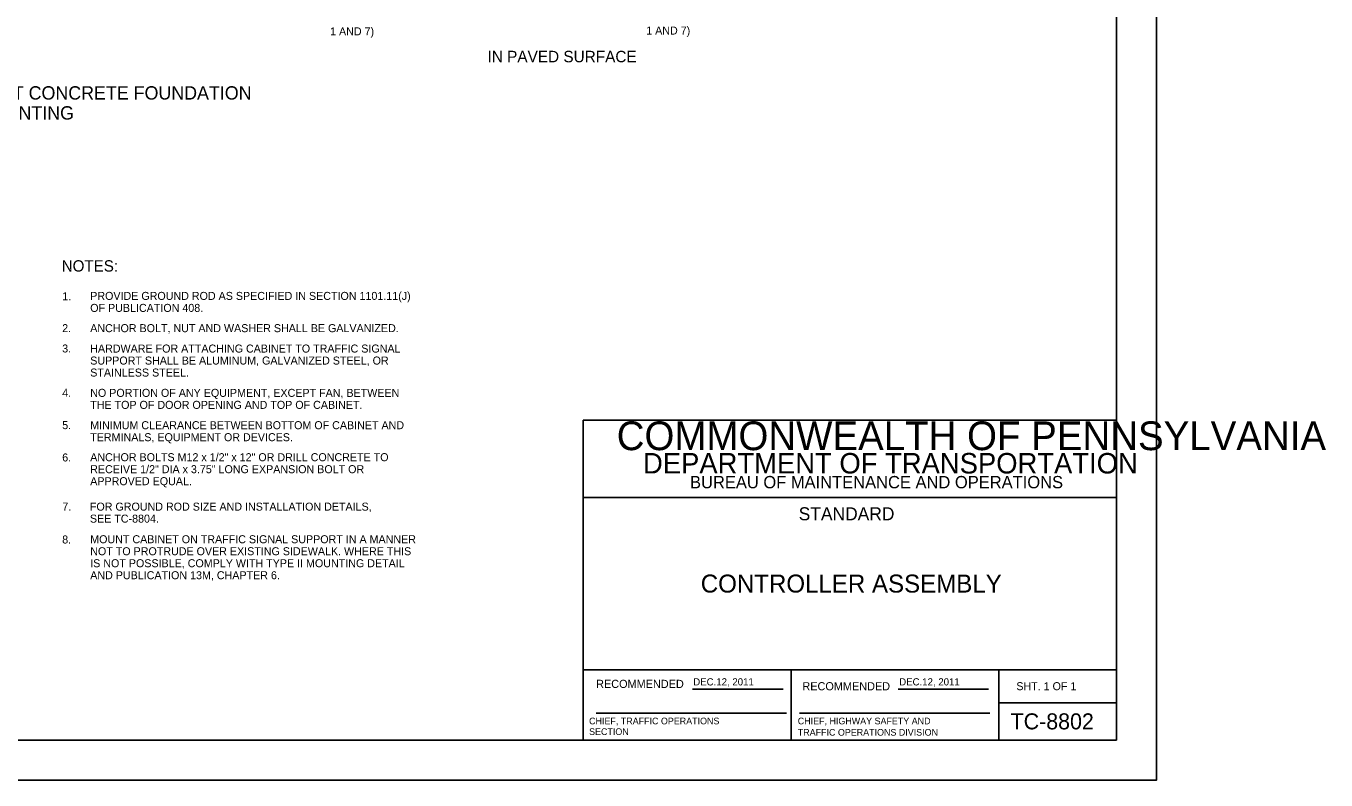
# Model space of a CAD drawing. Extents: x -855 to 49, y 616 to 1210.
# Drawn here: x -438 to 49.4, y 616.2 to 899 of the extents above; entities that cross this region are included whole.
import ezdxf

# ---------------------------------------------------------------- set-up
doc = ezdxf.new("R2010")
doc.units = 0
for name, color, linetype in [('1', 7, 'Continuous'), ('2', 7, 'Continuous'), ('4', 7, 'Continuous'), ('Default', 7, 'Continuous'), ('PLT-BNDY', 7, 'Continuous')]:
    doc.layers.add(name, color=color, linetype=linetype)

msp = doc.modelspace()

# ---------------------------------------------------------------- linework, layer by layer
at = {"layer": '1'}
for p, q in [((-29.14, 631.17), (-29.14, 1195.17)), ((-229.14, 631.17), (-229.14, 751.17)), ((-229.14, 751.17), (-29.14, 751.17)), ((-29.14, 722.17), (-229.14, 722.17)), ((-229.14, 657.55), (-29.14, 657.55)), ((-151.14, 657.55), (-151.14, 631.17)), ((-73.27, 631.17), (-73.27, 657.55)), ((-188.1, 650.2), (-154.18, 650.2)), ((-111.01, 650.2), (-77.09, 650.2)), ((-73.27, 645.17), (-29.14, 645.17)), ((-224.26, 641.21), (-152.93, 641.21)), ((-148.05, 641.21), (-76.59, 641.21)), ((-29.14, 631.17), (-815.14, 631.17)), ((-815.14, 631.17), (-229.14, 631.17))]:
    msp.add_line(p, q, dxfattribs=at)
at = {"layer": 'PLT-BNDY'}
msp.add_lwpolyline([(-855.14, 1210.17), (-14.14, 1210.17), (-14.14, 616.17), (-855.14, 616.17)], close=True, dxfattribs=at)

# ---------------------------------------------------------------- texts
at = {"layer": '1'}
for s, height, p in [('COMMONWEALTH OF PENNSYLVANIA', 10.7828, (-216.55, 739.9)), ('DEPARTMENT OF TRANSPORTATION', 7.6837, (-206.69, 731.15)), ('BUREAU OF MAINTENANCE AND OPERATIONS', 4.6253, (-189.05, 725.59)), ('CONTROLLER ASSEMBLY', 6.75, (-185.03, 686.48)), ('RECOMMENDED', 3.0516, (-224.27, 650.7)), ('RECOMMENDED', 3.0516, (-146.92, 649.82)), ('SHT. 1 OF 1', 3, (-66.71, 649.86)), ('TC-8802', 6, (-68.86, 635.17))]:
    msp.add_text(s, height=height, dxfattribs=at).set_placement(p)
at = {"layer": '2'}
for s, height, p in [('1 AND 7)', 3, (-324.01, 895.49)), ('1 AND 7)', 3, (-205.48, 895.79)), ('IN PAVED SURFACE', 4.3, (-264.98, 885.39)), ('CONTROLLER ASSEMBLY ON CEMENT CONCRETE FOUNDATION', 5, (-564.48, 871.41)), ('TYPE I MOUNTING', 5, (-479.48, 863.91)), ('NOTES:', 4.25, (-424.66, 806.89)), ('PROVIDE GROUND ROD AS SPECIFIED IN SECTION 1101.11(J) ', 3, (-413.96, 796.26)), ('1.', 3, (-424.41, 796.15)), ('OF PUBLICATION 408.', 3, (-413.96, 791.76)), ('2.', 3, (-424.46, 784.16)), ('ANCHOR BOLT, NUT AND WASHER SHALL BE GALVANIZED.', 3, (-413.96, 784.16)), ('3.', 3, (-424.46, 776.54)), ('SUPPORT SHALL BE ALUMINUM, GALVANIZED STEEL, OR', 3, (-413.96, 772.01)), ('HARDWARE FOR ATTACHING CABINET TO TRAFFIC SIGNAL', 3, (-413.96, 776.51)), ('STAINLESS STEEL.', 3, (-413.96, 767.51)), ('4.', 3, (-424.46, 759.91)), ('NO PORTION OF ANY EQUIPMENT, EXCEPT FAN, BETWEEN', 3, (-413.96, 759.89)), ('THE TOP OF DOOR OPENING AND TOP OF CABINET.', 3, (-413.96, 755.39)), ('5.', 3, (-424.46, 747.79)), ('MINIMUM CLEARANCE BETWEEN BOTTOM OF CABINET AND', 3, (-413.96, 747.76)), ('TERMINALS, EQUIPMENT OR DEVICES.', 3, (-413.96, 743.26)), ('6.', 3, (-424.46, 735.66)), ('ANCHOR BOLTS M12 x 1/2" x 12" OR DRILL CONCRETE TO', 3, (-413.96, 735.76)), ('RECEIVE 1/2" DIA x 3.75" LONG EXPANSION BOLT OR', 3, (-413.96, 731.26)), ('APPROVED EQUAL.', 3, (-413.96, 726.76)), ('7.', 3, (-424.42, 717.22)), ('FOR GROUND ROD SIZE AND INSTALLATION DETAILS,', 3, (-414.08, 717.22)), ('SEE TC-8804.', 3, (-414.08, 712.72)), ('8.', 3, (-424.46, 704.88)), ('MOUNT CABINET ON TRAFFIC SIGNAL SUPPORT IN A MANNER', 3, (-413.96, 704.98)), ('NOT TO PROTRUDE OVER EXISTING SIDEWALK. WHERE THIS', 3, (-413.96, 700.48)), ('IS NOT POSSIBLE, COMPLY WITH TYPE II MOUNTING DETAIL', 3, (-413.96, 695.98)), ('AND PUBLICATION 13M, CHAPTER 6.', 3, (-413.96, 691.48)), ('DEC.12, 2011', 2.7032, (-187.85, 651.64))]:
    msp.add_text(s, height=height, dxfattribs=at).set_placement(p)
msp.add_text('DEC.12, 2011', height=2.7032, rotation=360, dxfattribs=at).set_placement((-110.63, 651.64))
at = {"layer": '4'}
msp.add_text('STANDARD', height=4.881, rotation=360, dxfattribs=at).set_placement((-148.31, 713.59))
at = {"layer": 'Default'}
for s, p in [('CHIEF, TRAFFIC OPERATIONS', (-226.9, 637.06)), ('CHIEF, HIGHWAY SAFETY AND', (-148.65, 637.06)), ('SECTION', (-226.9, 633.06)), ('TRAFFIC OPERATIONS DIVISION', (-148.65, 632.81))]:
    msp.add_text(s, height=2.5, dxfattribs=at).set_placement(p)

doc.saveas('drawing.dxf')
